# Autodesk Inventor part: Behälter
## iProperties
Created: 2005-10
Part Number: Behälter
Material: Glas
Document SubType Name: Modeling
Designer: rsc
Manufacturer: Standard
Standards Organization: Custom
Kanten: brechen
Oberflächen: Ra 3,2
Radien: 2
Toleranzen: ISO 2768 - m
Author: rsc
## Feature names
1. Wandstärke1
2. Deckel mit Flansch [Extrusion]
3. Bohrung2 [Hole]
4. Runde Anordnung1 [Circular Pattern]
5. Bohrung3 [Hole]
6. Runde Anordnung2 [Circular Pattern]
7. Bohrung1 [Hole]
8. Abgeleiteter Körper1 [Tagging]
